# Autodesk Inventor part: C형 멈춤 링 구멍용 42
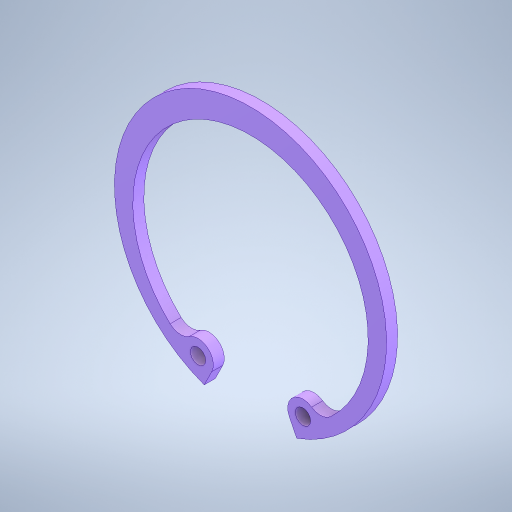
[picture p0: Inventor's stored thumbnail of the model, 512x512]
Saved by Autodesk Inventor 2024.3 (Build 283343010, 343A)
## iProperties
Created: 2025-11
Part Number: C형 멈춤 링 구멍용 42
Material: 강철, 연강
Description: 리테이닝 링(C형)
Document SubType Name: Modeling
Designer: PC2-15
Density: 7.85 g/cm^3
Appearance: 기본값
Author: jhkim
Sending System: Autodesk Inventor 2026
Preprocessor: ST-DEVELOPER v20.1
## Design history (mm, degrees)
node "C형 멈춤링 구멍용 421"
node "솔리드1"
body "Solid1"
